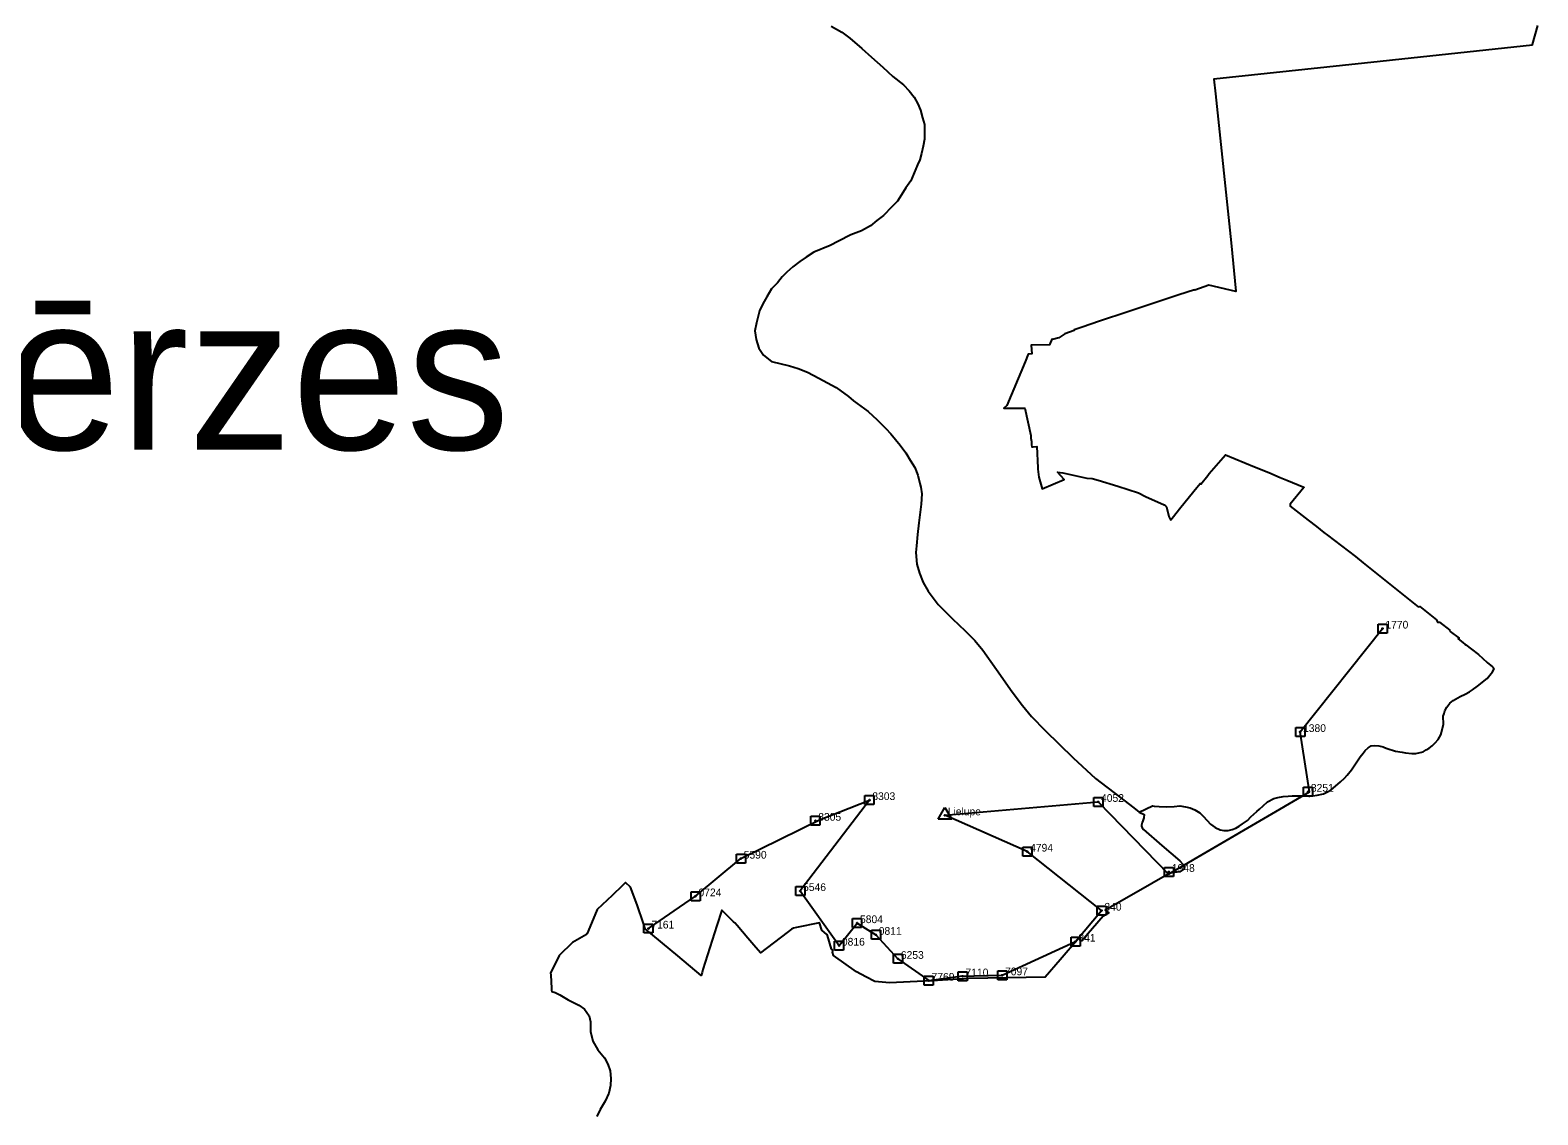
# Model space of a CAD drawing. Extents: x 462479 to 502016, y 241775 to 305873.
# Drawn here: x 472880 to 484614, y 280240 to 288685 of the extents above; entities that cross this region are included whole.
import ezdxf

# ---------------------------------------------------------------- set-up
doc = ezdxf.new("R2010")
doc.units = 0
for name, color, linetype in [('Default', 7, 'Continuous'), ('Level 19', 7, 'Continuous'), ('Level 51', 7, 'Continuous'), ('novada_robeza', 7, 'Continuous'), ('pagastu_nosaukumi', 7, 'Continuous'), ('pagastu_robezas', 7, 'Continuous')]:
    doc.layers.add(name, color=color, linetype=linetype)

msp = doc.modelspace()

# ---------------------------------------------------------------- linework, layer by layer
at = {"layer": 'Default'}
msp.add_lwpolyline([(477692, 281691), (478059, 281942), (478411, 282235), (479022, 282536), (479412, 282691), (478873, 281983), (479175, 281558), (479316, 281733), (479462, 281642), (479634, 281455), (479873, 281285), (480119, 281319), (480445, 281327), (481016, 281589), (481218, 281830), (480640, 282290), (479999, 282572), (481192, 282677), (481738, 282115), (482837, 282754), (482764, 283221), (483405, 284026)], dxfattribs=at)
at = {"layer": 'Level 19'}
for p, q in [((483370, 284061), (483440, 284061)), ((483370, 283991), (483370, 284061)), ((483440, 283991), (483370, 283991)), ((483440, 284061), (483440, 283991)), ((482729, 283256), (482799, 283256)), ((482729, 283186), (482729, 283256)), ((482729, 283256), (482799, 283256)), ((482729, 283186), (482729, 283256)), ((482799, 283256), (482799, 283186)), ((482799, 283256), (482799, 283186)), ((482799, 283186), (482729, 283186)), ((482799, 283186), (482729, 283186)), ((482790, 282791), (482860, 282791)), ((482790, 282721), (482790, 282791)), ((482860, 282791), (482860, 282721)), ((479377, 282726), (479447, 282726)), ((479377, 282656), (479377, 282726)), ((479447, 282726), (479447, 282656)), ((481157, 282712), (481227, 282712)), ((481157, 282642), (481157, 282712)), ((481227, 282712), (481227, 282642)), ((482860, 282721), (482790, 282721)), ((478956, 282565), (479026, 282565)), ((478956, 282495), (478956, 282565)), ((479026, 282565), (479026, 282495)), ((479447, 282656), (479377, 282656)), ((479946, 282541), (479999, 282632)), ((479999, 282632), (480052, 282541)), ((481227, 282642), (481157, 282642)), ((479026, 282495), (478956, 282495)), ((480052, 282541), (479946, 282541)), ((480605, 282325), (480675, 282325)), ((480605, 282255), (480605, 282325)), ((480675, 282325), (480675, 282255)), ((478376, 282270), (478446, 282270)), ((478376, 282200), (478376, 282270)), ((478376, 282270), (478446, 282270)), ((478376, 282200), (478376, 282270)), ((478446, 282200), (478376, 282200)), ((478446, 282200), (478376, 282200)), ((478446, 282270), (478446, 282200)), ((478446, 282270), (478446, 282200)), ((480675, 282255), (480605, 282255)), ((481708, 282167), (481778, 282167)), ((481708, 282097), (481708, 282167)), ((481708, 282167), (481778, 282167)), ((481708, 282097), (481708, 282167)), ((481708, 282167), (481778, 282167)), ((481708, 282097), (481708, 282167)), ((481778, 282097), (481708, 282097)), ((481778, 282097), (481708, 282097)), ((481778, 282097), (481708, 282097)), ((481778, 282167), (481778, 282097)), ((481778, 282167), (481778, 282097)), ((481778, 282167), (481778, 282097)), ((478024, 281977), (478094, 281977)), ((478024, 281907), (478024, 281977)), ((478094, 281977), (478094, 281907)), ((478838, 282018), (478908, 282018)), ((478838, 281948), (478838, 282018)), ((478908, 282018), (478908, 281948)), ((478094, 281907), (478024, 281907)), ((478908, 281948), (478838, 281948)), ((481183, 281865), (481253, 281865)), ((481183, 281795), (481183, 281865)), ((481253, 281865), (481253, 281795)), ((479281, 281768), (479351, 281768)), ((479281, 281698), (479281, 281768)), ((479281, 281768), (479351, 281768)), ((479281, 281698), (479281, 281768)), ((479281, 281768), (479351, 281768)), ((479281, 281698), (479281, 281768)), ((479351, 281768), (479351, 281698)), ((479351, 281768), (479351, 281698)), ((479351, 281768), (479351, 281698)), ((481253, 281795), (481183, 281795)), ((477657, 281726), (477727, 281726)), ((477657, 281656), (477657, 281726)), ((477727, 281656), (477657, 281656)), ((477727, 281726), (477727, 281656)), ((479351, 281698), (479281, 281698)), ((479351, 281698), (479281, 281698)), ((479351, 281698), (479281, 281698)), ((479427, 281677), (479497, 281677)), ((479427, 281607), (479427, 281677)), ((479497, 281677), (479497, 281607)), ((480981, 281624), (481051, 281624)), ((480981, 281554), (480981, 281624)), ((481051, 281624), (481051, 281554)), ((479140, 281593), (479210, 281593)), ((479140, 281523), (479140, 281593)), ((479210, 281523), (479140, 281523)), ((479210, 281593), (479210, 281523)), ((479497, 281607), (479427, 281607)), ((481051, 281554), (480981, 281554)), ((479599, 281490), (479669, 281490)), ((479599, 281420), (479599, 281490)), ((479669, 281420), (479599, 281420)), ((479669, 281490), (479669, 281420)), ((479838, 281320), (479908, 281320)), ((479838, 281250), (479838, 281320)), ((479908, 281320), (479908, 281250)), ((480102, 281354), (480172, 281354)), ((480102, 281284), (480102, 281354)), ((480172, 281284), (480102, 281284)), ((480172, 281354), (480172, 281284)), ((480410, 281362), (480480, 281362)), ((480410, 281292), (480410, 281362)), ((480480, 281292), (480410, 281292)), ((480480, 281362), (480480, 281292)), ((479908, 281250), (479838, 281250))]:
    msp.add_line(p, q, dxfattribs=at)
for centre in [(483405, 284026), (482764, 283221), (482764, 283221), (479412, 282691), (481192, 282677), (482825, 282756), (479999, 282572), (478991, 282530), (478411, 282235), (478411, 282235), (480640, 282290), (481743, 282132), (481743, 282132), (481743, 282132), (478873, 281983), (478059, 281942), (479316, 281733), (479316, 281733), (479316, 281733), (481218, 281830), (477692, 281690), (479462, 281642), (479175, 281558), (481016, 281589), (479634, 281455), (479873, 281285), (480137, 281319), (480445, 281327)]:
    msp.add_circle(centre, 3.5, dxfattribs=at)
at = {"layer": 'novada_robeza'}
for points in [[(484571, 288568), (484571, 288572), (484614, 288720)], [(484571, 288568), (483555, 288459), (483386, 288441), (482092, 288302), (482104, 288190), (482227, 287030), (482264, 286652), (482264, 286649), (482052, 286698), (481943, 286661), (481941, 286662), (481820, 286624), (481556, 286537), (481424, 286492), (481203, 286418), (481067, 286373), (481004, 286352), (481005, 286346), (480932, 286321), (480887, 286289), (480837, 286277), (480832, 286279), (480814, 286234), (480671, 286233), (480675, 286164), (480648, 286162), (480624, 286103), (480480, 285762), (480457, 285742), (480466, 285742), (480496, 285742), (480526, 285743), (480564, 285743), (480566, 285743), (480620, 285743), (480667, 285529), (480669, 285507), (480672, 285481), (480674, 285455), (480676, 285440), (480687, 285440), (480714, 285442), (480722, 285278), (480723, 285268), (480731, 285204), (480757, 285114), (480926, 285187), (480875, 285244), (480917, 285238), (481104, 285197), (481145, 285194), (481192, 285181), (481345, 285134), (481507, 285082), (481561, 285053), (481705, 284988), (481715, 284982), (481724, 284973), (481741, 284899), (481754, 284873), (481760, 284876), (481768, 284886), (481836, 284971), (481960, 285125), (481987, 285155), (481991, 285151), (482046, 285218), (482057, 285232), (482182, 285379), (482408, 285286), (482519, 285240), (482608, 285203), (482661, 285180), (482793, 285126), (482792, 285125), (482685, 284994), (482685, 284980), (482687, 284979), (482826, 284871), (482891, 284820), (482949, 284775), (482976, 284754), (483194, 284586), (483254, 284538), (483683, 284194), (483696, 284198), (483825, 284095), (483834, 284077), (483848, 284077), (483928, 284014), (483932, 284004), (484001, 283951), (483993, 283947), (484030, 283918), (484049, 283903), (484053, 283900), (484098, 283866), (484151, 283823), (484220, 283763), (484260, 283728), (484266, 283723), (484275, 283712)], [(483420, 283101), (483442, 283093), (483505, 283072), (483559, 283063), (483584, 283059), (483634, 283053), (483665, 283054), (483720, 283066), (483744, 283081), (483769, 283095), (483791, 283113), (483814, 283137), (483838, 283163), (483858, 283198), (483865, 283216), (483879, 283283), (483878, 283344), (483884, 283366), (483889, 283385), (483906, 283413), (483930, 283445), (483955, 283465), (484009, 283496), (484048, 283516), (484083, 283533), (484106, 283548), (484145, 283577), (484220, 283637), (484262, 283690), (484275, 283712)], [(481511, 282597), (481614, 282646), (481629, 282644), (481667, 282640), (481724, 282637), (481783, 282642), (481827, 282645), (481872, 282639), (481908, 282631), (481945, 282614), (481982, 282591), (482011, 282564), (482067, 282503), (482102, 282477), (482141, 282459), (482171, 282453), (482204, 282454), (482235, 282461), (482263, 282472), (482288, 282488), (482315, 282507), (482353, 282533), (482380, 282560), (482403, 282580), (482428, 282602), (482448, 282621), (482477, 282645), (482511, 282676), (482559, 282703), (482590, 282712), (482632, 282719), (482670, 282721), (482702, 282724), (482749, 282723), (482799, 282724), (482807, 282723), (482831, 282722), (482840, 282722), (482863, 282724), (482897, 282730), (482946, 282740), (482977, 282754), (483004, 282771), (483040, 282800), (483078, 282833), (483108, 282861), (483129, 282884), (483164, 282925), (483211, 282997), (483230, 283027), (483253, 283056), (483271, 283077), (483294, 283098), (483317, 283113), (483345, 283116), (483375, 283113), (483409, 283105), (483420, 283101)], [(481511, 282597), (481551, 282578), (481547, 282552), (481540, 282530), (481534, 282515), (481531, 282506), (481528, 282496), (481529, 282488), (481535, 282475), (481544, 282461), (481688, 282338), (481828, 282217), (481851, 282192), (481856, 282186), (481859, 282177), (481860, 282156), (481860, 282155), (481827, 282131), (481750, 282122), (481469, 281962), (481247, 281835), (481274, 281814), (481231, 281787), (481066, 281595), (481040, 281612), (480897, 281447), (480779, 281311), (480185, 281301), (479900, 281283), (479837, 281281), (479569, 281269), (479455, 281278), (479383, 281316), (479312, 281354), (479132, 281480), (479123, 281507), (479127, 281516), (479116, 281531), (479085, 281637), (479081, 281645), (479042, 281679), (479024, 281736), (478844, 281698), (478822, 281693), (478805, 281685), (478771, 281660), (478564, 281501), (478512, 281562), (478465, 281616), (478382, 281715), (478364, 281734), (478355, 281743), (478276, 281822), (478263, 281835), (478224, 281714), (478188, 281600), (478115, 281371), (478109, 281348), (478103, 281324), (477920, 281477), (477666, 281688), (477654, 281731), (477603, 281875), (477553, 282012), (477514, 282049), (477490, 282026), (477410, 281949), (477294, 281838), (477249, 281733), (477215, 281652), (477211, 281644), (477102, 281583), (476996, 281480), (476952, 281390), (476930, 281345), (476931, 281327), (476937, 281226), (476938, 281212), (476939, 281200), (476966, 281193), (477003, 281175), (477068, 281136), (477150, 281093), (477195, 281064), (477230, 281011), (477242, 280964), (477242, 280890), (477258, 280815), (477299, 280746), (477349, 280684), (477377, 280634), (477393, 280584), (477399, 280524), (477396, 280468), (477383, 280408), (477355, 280347), (477317, 280283), (477290, 280227)]]:
    msp.add_lwpolyline(points, dxfattribs=at)
at = {"layer": 'pagastu_robezas'}
msp.add_lwpolyline([(479114, 288715), (479197, 288669), (479258, 288622), (479353, 288542), (479427, 288475), (479517, 288397), (479595, 288324), (479676, 288258), (479722, 288211), (479760, 288162), (479788, 288112), (479810, 288061), (479825, 288003), (479839, 287950), (479840, 287895), (479839, 287835), (479831, 287782), (479817, 287724), (479803, 287676), (479787, 287635), (479733, 287512), (479696, 287457), (479660, 287402), (479629, 287353), (479587, 287310), (479520, 287241), (479469, 287203), (479421, 287162), (479350, 287121), (479268, 287092), (479171, 287041), (479106, 287008), (478979, 286957), (478920, 286918), (478871, 286883), (478816, 286843), (478769, 286800), (478732, 286765), (478695, 286718), (478650, 286670), (478614, 286608), (478582, 286553), (478556, 286499), (478533, 286405), (478519, 286345), (478529, 286276), (478551, 286208), (478588, 286155), (478649, 286104), (478789, 286070), (478858, 286050), (478929, 286023), (479017, 285976), (479152, 285902), (479250, 285832), (479289, 285798), (479403, 285717), (479471, 285651), (479539, 285584), (479579, 285543), (479650, 285454), (479696, 285395), (479728, 285338), (479765, 285280), (479789, 285220), (479805, 285156), (479813, 285126), (479820, 285075), (479815, 284995), (479795, 284849), (479785, 284757), (479777, 284671), (479773, 284617), (479781, 284527), (479802, 284457), (479829, 284384), (479868, 284317), (479947, 284214), (480059, 284102), (480158, 284007), (480232, 283932), (480294, 283857), (480400, 283707), (480522, 283534), (480603, 283427), (480673, 283341), (480779, 283233), (480998, 283019), (481171, 282860), (481358, 282717), (481470, 282631), (481511, 282597)], dxfattribs=at)

# ---------------------------------------------------------------- texts
at = {"layer": 'Level 51'}
for s, p in [(' 1770', (483405, 284026)), (' 1380', (482764, 283221)), (' 1380', (482764, 283221)), (' 8251', (482825, 282756)), (' 8303', (479412, 282691)), (' 4052', (481192, 282677)), (' 8305', (478991, 282530)), (' Lielupe', (479999, 282572)), (' 4794', (480640, 282290)), (' 5590', (478411, 282235)), (' 5590', (478411, 282235)), (' 1948', (481743, 282132)), (' 1948', (481743, 282132)), (' 1948', (481743, 282132)), (' 0724', (478059, 281942)), (' 5546', (478873, 281983)), (' 340', (481218, 281830)), (' 7161', (477692, 281691)), (' 5804', (479316, 281733)), (' 5804', (479316, 281733)), (' 5804', (479316, 281733)), (' 0816', (479175, 281558)), (' 0811', (479462, 281642)), (' 341', (481016, 281589)), (' 6253', (479634, 281455)), (' 7110', (480137, 281319)), (' 7097', (480445, 281327)), (' 7769', (479873, 281285))]:
    msp.add_text(s, height=60, dxfattribs=at).set_placement(p)
at = {"layer": 'pagastu_nosaukumi'}
msp.add_text('Līvbērzes', height=1200, dxfattribs=at).set_placement((469654, 285419))

doc.saveas('drawing.dxf')
